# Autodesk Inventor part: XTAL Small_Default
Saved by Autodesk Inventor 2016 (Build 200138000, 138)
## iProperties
Created: 2012-01
Part Number: XTAL Small_Default
Document SubType Name: Modeling
Designer: Trevor
Density: 1 g/cm^3
Material: Generic
Appearance: Default
Author: Trevor
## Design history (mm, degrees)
feature "Base1"
node "Boss-Extrude2"
